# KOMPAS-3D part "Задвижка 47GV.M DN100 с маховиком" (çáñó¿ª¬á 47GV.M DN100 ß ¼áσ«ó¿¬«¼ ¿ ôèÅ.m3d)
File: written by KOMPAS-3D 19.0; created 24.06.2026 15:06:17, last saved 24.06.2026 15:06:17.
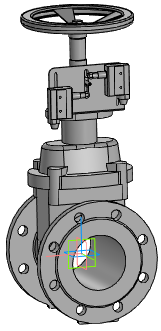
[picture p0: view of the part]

Document properties: Автор: Энергия; Полное имя файла: Z:\3.Личные\sachek\Dendor\3D для проектировщиков\2.7 Тип 47GV.M Задвижка клиновая фланцевая с обрезиненным клином\47GV.M DN100\Задвижка 47GV.M DN100 с маховиком.a3d

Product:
- Part/product: Задвижка 47GV.M DN100 с маховиком
    Масса: 28.5878
    source file: ..\47GV.M DN100\DR.47GVM.080.16.00.00 - Задвижка с обрезиненным клином DN80.spw
  - Component: Задвижка с обрезиненным клином DN80. Сборочный чертеж  | designation DR.47GVM.080.16.00.00СБ  | pos. 0  | Масса: 15.8764; Раздел спецификации: Документация; Форматы листов документа: 2xA3; source file: ..\47GV.M DN100\DR.47GVM.080.16.00.000 СБ - Задвижка с обрезиненным клином DN80.cdw
- Part/product: Задвижка 47GV.M DN100 с маховиком  | designation 01
    Масса: 15.8677
  - Component [standard]: Болт М10-6gx20-А2-70 ГОСТ 7798-70  | pos. 12  | Масса: 0.02379; Раздел спецификации: Стандартные изделия; Рассекать на разрезах: no
  - Component [standard]: Шайба1021695878  | pos. 20  | Материал: Сталь 12Х18Н10Т ГОСТ 5632-2014 (density 1000 kg/m3); Масса: 0.0121728; Раздел спецификации: Стандартные изделия; Рассекать на разрезах: no; additional columns: ГОСТ 6958-78; A 10.21
  - Component [detail]: Маховик 200  | pos. 20  | Масса: 0.448137; Раздел спецификации: Прочие изделия; source file: ..\..\..\47GVM\DR.47GVM.100.16.00.000\Маховик 200.m3d
  - Component [detail]: Крышка DN100  | pos. 4  | Материал: ВЧ50 ГОСТ 7293-85 (density 7200 kg/m3); Масса: 6.92658; Раздел спецификации: Детали; Форматы листов документа: 2xA3; source file: ..\47GV.M DN100\DR.47GVM.100.16.00.002 - Крышка.cdw, ..\47GV.M DN100\Крышка DN100.m3d
  - Component [detail]: Корпус DN100  | pos. 3  | Материал: ВЧ50 ГОСТ 7293-85 (density 7200 kg/m3); Масса: 19.2555; Раздел спецификации: Детали; Форматы листов документа: 2xA3; source file: ..\47GV.M DN100\DR.47GV.100.16.00.001 - Корпус.cdw, ..\47GV.M DN100\DR.47GVM.050.16.00.001 - Корпус.cdw, ..\47GV.M DN100\DR.47GVM.100.16.00.001 - Корпус.cdw, ..\47GV.M DN100\Корпус DN100.m3d
  - Component [assembly]: Клин с направляющими  | designation DR.47GVM.080.16.01.000  | pos. 4  | Раздел спецификации: Сборочные единицы; Форматы листов документа: A4; source file: ..\47GV.M DN100\DR.47GVM.080.16.01.000 - Клин с направляющими.a3d, ..\47GV.M DN100\DR.47GVM.080.16.01.000 - Клин с направляющими.spw, ..\47GV.M DN100\DR.47GVM.080.16.01.000 СБ - Клин с направляющими.cdw
  - Component [detail]: Шпиндель  | pos. 5  | Материал: Сталь 20Х13 ГОСТ 5632 - 2014 (density 7670 kg/m3); Масса: 0.114456; Раздел спецификации: Детали; Форматы листов документа: A3; source file: ..\47GV.M DN80\DR.47GVM.080.16.00.003 - Шпиндель.cdw, ..\47GV.M DN80\Шпиндель DN80.m3d
  - Component: Насадка для УКП  | designation DR.47GVM.UKP.100.16.00.001  | Материал: Сталь 08Х18Н10 ГОСТ 5632-2014 (density 7900 kg/m3); Масса: 0.521898; source file: ..\47GV.M DN80\DR.47GVM.UKP.100.16.00.001 - Насадка для УКП.cdw, ..\47GV.M DN80\DR.47GVM.UKP.100.16.00.001 Насадка для УКП.m3d
  - Component: Кронштейн  | designation DR.47GVM.UKP.100.16.00.002  | Материал: Ст3сп ГОСТ 380-2005 (density 7850 kg/m3); Масса: 0.15921; source file: ..\47GV.M DN80\DR.47GVM.UKP.100.16.00.002 - Кронштейн.cdw, ..\47GV.M DN80\DR.47GVM.UKP.100.16.00.002 - Кронштейн.m3d
  - Component: Контргайка  | designation DR.47GVM.UKP.100.16.00.003  | Материал: Сталь 08Х18Н10 ГОСТ 5632-2014 (density 7900 kg/m3); Масса: 0.103544; source file: ..\47GV.M DN80\DR.47GVM.UKP.100.16.00.003 - Контргайка.cdw, ..\47GV.M DN80\DR.47GVM.UKP.100.16.00.003 - Контргайка.m3d
  - Component: Винт установочный М6х45  | designation DR.47GVM.UKP.050.16.00.005  | Материал: Сталь 08Х18Н10 ГОСТ 5632-2014 (density 7900 kg/m3); Масса: 0.00994284; source file: ..\47GV.M DN50\DR.47GVM.UKP.050.16.00.005 Винт установочный.m3d
  - Component: Концевик AZ7311  | qty 2  | Масса: 0.377378; source file: ..\47GV.M DN50\Концевик AZ7311.m3d

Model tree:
1. Операция без истории:1

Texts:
  Точка начала. Х
  Точка начала. Y
  Точка начала. Z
